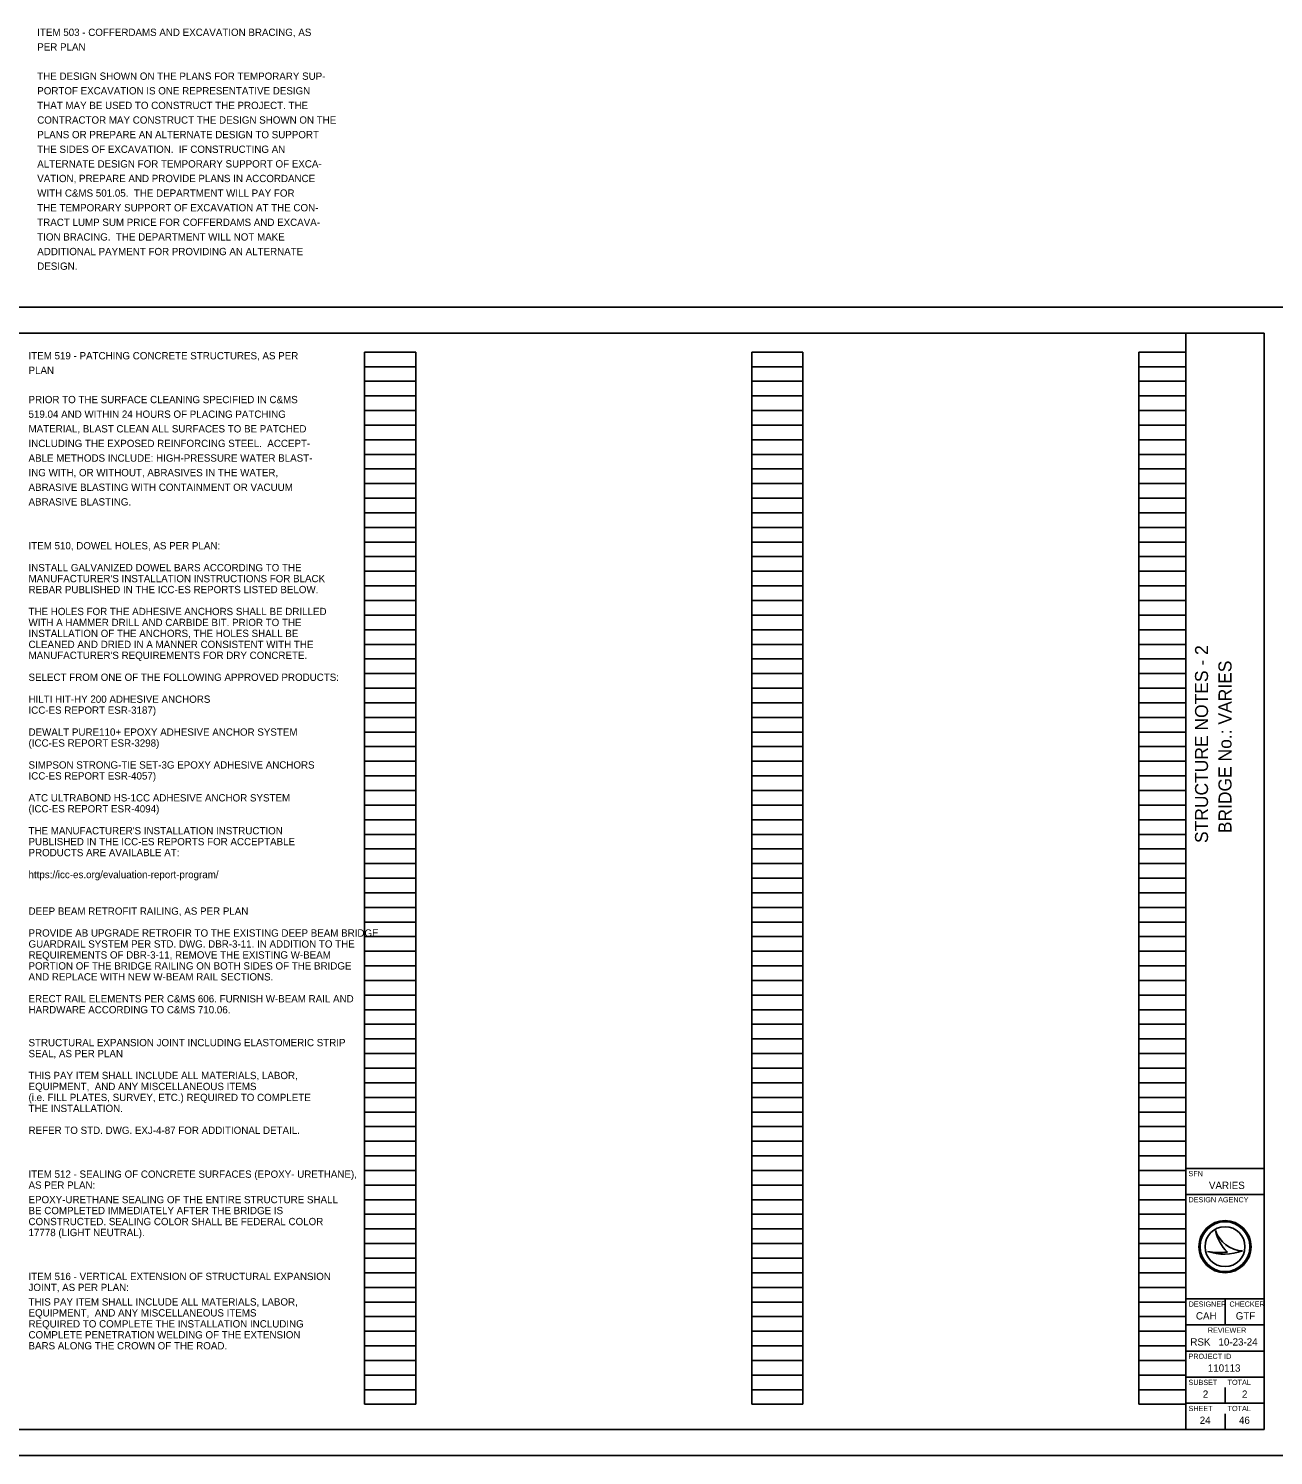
# Model space of a CAD drawing. Extents: x -11.4 to 74.5, y -13.7 to 46.2.
# Drawn here: x 9.82 to 33.68, y 0 to 27.34 of the extents above; entities that cross this region are included whole.
import ezdxf

# ---------------------------------------------------------------- set-up
doc = ezdxf.new("R2010")
doc.units = 0
for name, color, linetype in [('SC_Scratch1', 7, 'Continuous'), ('SH_Border', 7, 'Continuous'), ('SH_Cut_Line', 7, 'Continuous'), ('SH_Data', 7, 'Continuous'), ('SH_Text', 7, 'Continuous')]:
    doc.layers.add(name, color=color, linetype=linetype)

msp = doc.modelspace()

# ---------------------------------------------------------------- linework, layer by layer
at = {"layer": 'SC_Scratch1'}
for p, q in [((16.26, 0.98), (16.26, 21.14)), ((16.26, 21.14), (17.24, 21.14)), ((17.24, 0.98), (17.24, 21.14)), ((23.68, 0.98), (23.68, 21.14)), ((23.68, 21.14), (24.66, 21.14)), ((24.66, 0.98), (24.66, 21.14)), ((31.1, 0.98), (31.1, 21.14)), ((31.1, 21.14), (32, 21.14)), ((32, 0.98), (32, 21.14)), ((16.26, 20.86), (17.24, 20.86)), ((23.68, 20.86), (24.66, 20.86)), ((31.1, 20.86), (32, 20.86)), ((16.26, 20.58), (17.24, 20.58)), ((23.68, 20.58), (24.66, 20.58)), ((31.1, 20.58), (32, 20.58)), ((16.26, 20.3), (17.24, 20.3)), ((23.68, 20.3), (24.66, 20.3)), ((31.1, 20.3), (32, 20.3)), ((16.26, 20.02), (17.24, 20.02)), ((23.68, 20.02), (24.66, 20.02)), ((31.1, 20.02), (32, 20.02)), ((16.26, 19.74), (17.24, 19.74)), ((23.68, 19.74), (24.66, 19.74)), ((31.1, 19.74), (32, 19.74)), ((16.26, 19.46), (17.24, 19.46)), ((23.68, 19.46), (24.66, 19.46)), ((31.1, 19.46), (32, 19.46)), ((16.26, 19.18), (17.24, 19.18)), ((23.68, 19.18), (24.66, 19.18)), ((31.1, 19.18), (32, 19.18)), ((16.26, 18.9), (17.24, 18.9)), ((23.68, 18.9), (24.66, 18.9)), ((31.1, 18.9), (32, 18.9)), ((16.26, 18.62), (17.24, 18.62)), ((23.68, 18.62), (24.66, 18.62)), ((31.1, 18.62), (32, 18.62)), ((16.26, 18.34), (17.24, 18.34)), ((23.68, 18.34), (24.66, 18.34)), ((31.1, 18.34), (32, 18.34)), ((16.26, 18.06), (17.24, 18.06)), ((23.68, 18.06), (24.66, 18.06)), ((31.1, 18.06), (32, 18.06)), ((16.26, 17.78), (17.24, 17.78)), ((23.68, 17.78), (24.66, 17.78)), ((31.1, 17.78), (32, 17.78)), ((16.26, 17.5), (17.24, 17.5)), ((23.68, 17.5), (24.66, 17.5)), ((31.1, 17.5), (32, 17.5)), ((16.26, 17.22), (17.24, 17.22)), ((23.68, 17.22), (24.66, 17.22)), ((31.1, 17.22), (32, 17.22)), ((16.26, 16.94), (17.24, 16.94)), ((23.68, 16.94), (24.66, 16.94)), ((31.1, 16.94), (32, 16.94)), ((16.26, 16.66), (17.24, 16.66)), ((23.68, 16.66), (24.66, 16.66)), ((31.1, 16.66), (32, 16.66)), ((16.26, 16.38), (17.24, 16.38)), ((23.68, 16.38), (24.66, 16.38)), ((31.1, 16.38), (32, 16.38)), ((16.26, 16.1), (17.24, 16.1)), ((23.68, 16.1), (24.66, 16.1)), ((31.1, 16.1), (32, 16.1)), ((16.26, 15.82), (17.24, 15.82)), ((23.68, 15.82), (24.66, 15.82)), ((31.1, 15.82), (32, 15.82)), ((16.26, 15.54), (17.24, 15.54)), ((23.68, 15.54), (24.66, 15.54)), ((31.1, 15.54), (32, 15.54)), ((16.26, 15.26), (17.24, 15.26)), ((23.68, 15.26), (24.66, 15.26)), ((31.1, 15.26), (32, 15.26)), ((16.26, 14.98), (17.24, 14.98)), ((23.68, 14.98), (24.66, 14.98)), ((31.1, 14.98), (32, 14.98)), ((16.26, 14.7), (17.24, 14.7)), ((23.68, 14.7), (24.66, 14.7)), ((31.1, 14.7), (32, 14.7)), ((16.26, 14.42), (17.24, 14.42)), ((23.68, 14.42), (24.66, 14.42)), ((31.1, 14.42), (32, 14.42)), ((16.26, 14.14), (17.24, 14.14)), ((23.68, 14.14), (24.66, 14.14)), ((31.1, 14.14), (32, 14.14)), ((16.26, 13.86), (17.24, 13.86)), ((23.68, 13.86), (24.66, 13.86)), ((31.1, 13.86), (32, 13.86)), ((16.26, 13.58), (17.24, 13.58)), ((23.68, 13.58), (24.66, 13.58)), ((31.1, 13.58), (32, 13.58)), ((16.26, 13.3), (17.24, 13.3)), ((23.68, 13.3), (24.66, 13.3)), ((31.1, 13.3), (32, 13.3)), ((16.26, 13.02), (17.24, 13.02)), ((23.68, 13.02), (24.66, 13.02)), ((31.1, 13.02), (32, 13.02)), ((16.26, 12.74), (17.24, 12.74)), ((23.68, 12.74), (24.66, 12.74)), ((31.1, 12.74), (32, 12.74)), ((16.26, 12.46), (17.24, 12.46)), ((23.68, 12.46), (24.66, 12.46)), ((31.1, 12.46), (32, 12.46)), ((16.26, 12.18), (17.24, 12.18)), ((23.68, 12.18), (24.66, 12.18)), ((31.1, 12.18), (32, 12.18)), ((16.26, 11.9), (17.24, 11.9)), ((23.68, 11.9), (24.66, 11.9)), ((31.1, 11.9), (32, 11.9)), ((16.26, 11.62), (17.24, 11.62)), ((23.68, 11.62), (24.66, 11.62)), ((31.1, 11.62), (32, 11.62)), ((16.26, 11.34), (17.24, 11.34)), ((23.68, 11.34), (24.66, 11.34)), ((31.1, 11.34), (32, 11.34)), ((16.26, 11.06), (17.24, 11.06)), ((23.68, 11.06), (24.66, 11.06)), ((31.1, 11.06), (32, 11.06)), ((16.26, 10.78), (17.24, 10.78)), ((23.68, 10.78), (24.66, 10.78)), ((31.1, 10.78), (32, 10.78)), ((16.26, 10.5), (17.24, 10.5)), ((23.68, 10.5), (24.66, 10.5)), ((31.1, 10.5), (32, 10.5)), ((16.26, 10.22), (17.24, 10.22)), ((23.68, 10.22), (24.66, 10.22)), ((31.1, 10.22), (32, 10.22)), ((16.26, 9.94), (17.24, 9.94)), ((23.68, 9.94), (24.66, 9.94)), ((31.1, 9.94), (32, 9.94)), ((16.26, 9.66), (17.24, 9.66)), ((23.68, 9.66), (24.66, 9.66)), ((31.1, 9.66), (32, 9.66)), ((16.26, 9.38), (17.24, 9.38)), ((23.68, 9.38), (24.66, 9.38)), ((31.1, 9.38), (32, 9.38)), ((16.26, 9.1), (17.24, 9.1)), ((23.68, 9.1), (24.66, 9.1)), ((31.1, 9.1), (32, 9.1)), ((16.26, 8.82), (17.24, 8.82)), ((23.68, 8.82), (24.66, 8.82)), ((31.1, 8.82), (32, 8.82)), ((16.26, 8.54), (17.24, 8.54)), ((23.68, 8.54), (24.66, 8.54)), ((31.1, 8.54), (32, 8.54)), ((16.26, 8.26), (17.24, 8.26)), ((23.68, 8.26), (24.66, 8.26)), ((31.1, 8.26), (32, 8.26)), ((16.26, 7.98), (17.24, 7.98)), ((23.68, 7.98), (24.66, 7.98)), ((31.1, 7.98), (32, 7.98)), ((16.26, 7.7), (17.24, 7.7)), ((23.68, 7.7), (24.66, 7.7)), ((31.1, 7.7), (32, 7.7)), ((16.26, 7.42), (17.24, 7.42)), ((23.68, 7.42), (24.66, 7.42)), ((31.1, 7.42), (32, 7.42)), ((16.26, 7.14), (17.24, 7.14)), ((23.68, 7.14), (24.66, 7.14)), ((31.1, 7.14), (32, 7.14)), ((16.26, 6.86), (17.24, 6.86)), ((23.68, 6.86), (24.66, 6.86)), ((31.1, 6.86), (32, 6.86)), ((16.26, 6.58), (17.24, 6.58)), ((23.68, 6.58), (24.66, 6.58)), ((31.1, 6.58), (32, 6.58)), ((16.26, 6.3), (17.24, 6.3)), ((23.68, 6.3), (24.66, 6.3)), ((31.1, 6.3), (32, 6.3)), ((16.26, 6.02), (17.24, 6.02)), ((23.68, 6.02), (24.66, 6.02)), ((31.1, 6.02), (32, 6.02)), ((16.26, 5.74), (17.24, 5.74)), ((23.68, 5.74), (24.66, 5.74)), ((31.1, 5.74), (32, 5.74)), ((16.26, 5.46), (17.24, 5.46)), ((23.68, 5.46), (24.66, 5.46)), ((31.1, 5.46), (32, 5.46)), ((16.26, 5.18), (17.24, 5.18)), ((23.68, 5.18), (24.66, 5.18)), ((31.1, 5.18), (32, 5.18)), ((16.26, 4.9), (17.24, 4.9)), ((23.68, 4.9), (24.66, 4.9)), ((31.1, 4.9), (32, 4.9)), ((16.26, 4.62), (17.24, 4.62)), ((23.68, 4.62), (24.66, 4.62)), ((31.1, 4.62), (32, 4.62)), ((16.26, 4.34), (17.24, 4.34)), ((23.68, 4.34), (24.66, 4.34)), ((31.1, 4.34), (32, 4.34)), ((16.26, 4.06), (17.24, 4.06)), ((23.68, 4.06), (24.66, 4.06)), ((31.1, 4.06), (32, 4.06)), ((16.26, 3.78), (17.24, 3.78)), ((23.68, 3.78), (24.66, 3.78)), ((31.1, 3.78), (32, 3.78)), ((16.26, 3.5), (17.24, 3.5)), ((23.68, 3.5), (24.66, 3.5)), ((31.1, 3.5), (32, 3.5)), ((16.26, 3.22), (17.24, 3.22)), ((23.68, 3.22), (24.66, 3.22)), ((31.1, 3.22), (32, 3.22)), ((16.26, 2.94), (17.24, 2.94)), ((23.68, 2.94), (24.66, 2.94)), ((31.1, 2.94), (32, 2.94)), ((16.26, 2.66), (17.24, 2.66)), ((23.68, 2.66), (24.66, 2.66)), ((31.1, 2.66), (32, 2.66)), ((16.26, 2.38), (17.24, 2.38)), ((23.68, 2.38), (24.66, 2.38)), ((31.1, 2.38), (32, 2.38)), ((16.26, 2.1), (17.24, 2.1)), ((23.68, 2.1), (24.66, 2.1)), ((31.1, 2.1), (32, 2.1)), ((16.26, 1.82), (17.24, 1.82)), ((23.68, 1.82), (24.66, 1.82)), ((31.1, 1.82), (32, 1.82)), ((16.26, 1.54), (17.24, 1.54)), ((23.68, 1.54), (24.66, 1.54)), ((31.1, 1.54), (32, 1.54)), ((16.26, 1.26), (17.24, 1.26)), ((23.68, 1.26), (24.66, 1.26)), ((31.1, 1.26), (32, 1.26)), ((16.26, 0.98), (17.24, 0.98)), ((23.68, 0.98), (24.66, 0.98)), ((31.1, 0.98), (32, 0.98))]:
    msp.add_line(p, q, dxfattribs=at)
at = {"layer": 'SH_Border'}
for p, q in [((32, 0.5), (32, 21.5)), ((32, 5.5), (33.5, 5.5)), ((32, 5), (33.5, 5)), ((32, 3), (33.5, 3)), ((32.75, 3), (32.75, 2.5)), ((32, 2.5), (33.5, 2.5)), ((32, 2), (33.5, 2)), ((32, 1.5), (33.5, 1.5)), ((32, 1), (33.5, 1))]:
    msp.add_line(p, q, dxfattribs=at)
msp.add_lwpolyline([(1.5, 21.5), (33.5, 21.5), (33.5, 0.5), (1.5, 0.5)], close=True, dxfattribs=at)
at = {"layer": 'SH_Cut_Line'}
msp.add_lwpolyline([(0, 0), (34, 0), (34, 22), (0, 22)], close=True, dxfattribs=at)
at = {"layer": 'SH_Data'}
for p, q in [((32.567, 4.31), (32.567, 4.31)), ((32.417, 3.91), (32.417, 3.91)), ((32.75, 4), (32.75, 4)), ((33.087, 3.919), (33.087, 3.919)), ((32.75, 1), (32.75, 1.3)), ((32.375, 0.675), (32.375, 0.675)), ((32.75, 0.5), (32.75, 0.8))]:
    msp.add_line(p, q, dxfattribs=at)
for radius in [0.5, 0.477, 0.477, 0.382]:
    msp.add_circle((32.75, 4), radius, dxfattribs=at)
for centre, radius, start, end in [((33.116, 4.498), 0.58, 198.9257, 198.9319), ((33.347, 4.47), 0.796, 191.6379, 191.6421), ((33.116, 4.498), 0.58, 198.9319, 267.1657), ((33.347, 4.47), 0.796, 191.6421, 226.0947), ((32.739, 4.87), 1.013, 251.4576, 290.0832), ((32.648, 5.154), 1.266, 259.4964, 259.4995), ((32.739, 4.87), 1.013, 251.4527, 251.4576), ((32.648, 5.154), 1.266, 259.4995, 276.6672)]:
    msp.add_arc(centre, radius, start, end, dxfattribs=at)

# ---------------------------------------------------------------- texts
for s, p in [('STRUCTURE NOTES - 2', (32.425, 11.734)), ('BRIDGE No.: VARIES', (32.875, 11.922))]:
    msp.add_text(s, height=0.25, rotation=90, dxfattribs=at).set_placement(p)
for s, height, p in [('SFN', 0.1, (32.05, 5.35)), ('VARIES', 0.14, (32.442, 5.105)), ('DESIGN AGENCY', 0.1, (32.05, 4.85)), ('DESIGNER', 0.1, (32.054, 2.85)), ('CAH', 0.14, (32.193, 2.605)), ('CHECKER', 0.1, (32.835, 2.85)), ('GTF', 0.14, (32.956, 2.605)), ('RSK', 0.14, (32.086, 2.105)), ('REVIEWER', 0.1, (32.422, 2.35)), ('10-23-24', 0.14, (32.625, 2.105)), ('PROJECT ID', 0.1, (32.05, 1.85)), ('110113', 0.14, (32.421, 1.605)), ('SUBSET', 0.1, (32.05, 1.35)), ('TOTAL', 0.1, (32.8, 1.35)), ('2', 0.14, (32.325, 1.105)), ('2', 0.14, (33.075, 1.105)), ('SHEET', 0.1, (32.05, 0.85)), ('TOTAL', 0.1, (32.8, 0.85)), ('24', 0.14, (32.266, 0.605)), ('46', 0.14, (33.018, 0.605))]:
    msp.add_text(s, height=height, dxfattribs=at).set_placement(p)
at = {"layer": 'SH_Text'}
for s, p in [('ITEM 503 - COFFERDAMS AND EXCAVATION BRACING, AS', (9.987, 27.196)), ('PER PLAN', (9.987, 26.916)), ('THE DESIGN SHOWN ON THE PLANS FOR TEMPORARY SUP-', (9.987, 26.356)), ('PORTOF EXCAVATION IS ONE REPRESENTATIVE DESIGN', (9.987, 26.076)), ('THAT MAY BE USED TO CONSTRUCT THE PROJECT. THE', (9.987, 25.796)), ('CONTRACTOR MAY CONSTRUCT THE DESIGN SHOWN ON THE', (9.987, 25.516)), ('PLANS OR PREPARE AN ALTERNATE DESIGN TO SUPPORT', (9.987, 25.236)), ('THE SIDES OF EXCAVATION.  IF CONSTRUCTING AN', (9.987, 24.956)), ('ALTERNATE DESIGN FOR TEMPORARY SUPPORT OF EXCA-', (9.987, 24.676)), ('VATION, PREPARE AND PROVIDE PLANS IN ACCORDANCE', (9.987, 24.396)), ('WITH C&MS 501.05.  THE DEPARTMENT WILL PAY FOR', (9.987, 24.116)), ('THE TEMPORARY SUPPORT OF EXCAVATION AT THE CON-', (9.987, 23.836)), ('TRACT LUMP SUM PRICE FOR COFFERDAMS AND EXCAVA-', (9.987, 23.556)), ('TION BRACING.  THE DEPARTMENT WILL NOT MAKE', (9.987, 23.276)), ('ADDITIONAL PAYMENT FOR PROVIDING AN ALTERNATE', (9.987, 22.996)), ('DESIGN.', (9.987, 22.716)), ('ITEM 519 - PATCHING CONCRETE STRUCTURES, AS PER', (9.82, 21)), ('PLAN', (9.82, 20.72)), ('PRIOR TO THE SURFACE CLEANING SPECIFIED IN C&MS', (9.82, 20.16)), ('519.04 AND WITHIN 24 HOURS OF PLACING PATCHING', (9.82, 19.88)), ('MATERIAL, BLAST CLEAN ALL SURFACES TO BE PATCHED', (9.82, 19.6)), ('INCLUDING THE EXPOSED REINFORCING STEEL.  ACCEPT-', (9.82, 19.32)), ('ABLE METHODS INCLUDE: HIGH-PRESSURE WATER BLAST-', (9.82, 19.04)), ('ING WITH, OR WITHOUT, ABRASIVES IN THE WATER,', (9.82, 18.76)), ('ABRASIVE BLASTING WITH CONTAINMENT OR VACUUM', (9.82, 18.48)), ('ABRASIVE BLASTING.', (9.82, 18.2)), ('ITEM 510, DOWEL HOLES, AS PER PLAN:', (9.82, 17.36)), ('INSTALL GALVANIZED DOWEL BARS ACCORDING TO THE', (9.82, 16.94)), ("MANUFACTURER'S INSTALLATION INSTRUCTIONS FOR BLACK", (9.82, 16.73)), ('REBAR PUBLISHED IN THE ICC-ES REPORTS LISTED BELOW.', (9.82, 16.52)), ('THE HOLES FOR THE ADHESIVE ANCHORS SHALL BE DRILLED', (9.82, 16.1)), ('WITH A HAMMER DRILL AND CARBIDE BIT. PRIOR TO THE', (9.82, 15.89)), ('CLEANED AND DRIED IN A MANNER CONSISTENT WITH THE', (9.82, 15.47)), ('INSTALLATION OF THE ANCHORS, THE HOLES SHALL BE', (9.82, 15.68)), ("MANUFACTURER'S REQUIREMENTS FOR DRY CONCRETE.", (9.82, 15.26)), ('SELECT FROM ONE OF THE FOLLOWING APPROVED PRODUCTS:', (9.82, 14.84)), ('HILTI HIT-HY 200 ADHESIVE ANCHORS', (9.82, 14.42)), ('ICC-ES REPORT ESR-3187)', (9.82, 14.21)), ('(ICC-ES REPORT ESR-3298)', (9.82, 13.58)), ('DEWALT PURE110+ EPOXY ADHESIVE ANCHOR SYSTEM', (9.82, 13.79)), ('SIMPSON STRONG-TIE SET-3G EPOXY ADHESIVE ANCHORS', (9.82, 13.16)), ('ICC-ES REPORT ESR-4057)', (9.82, 12.95)), ('ATC ULTRABOND HS-1CC ADHESIVE ANCHOR SYSTEM', (9.82, 12.53)), ('(ICC-ES REPORT ESR-4094)', (9.82, 12.32)), ("THE MANUFACTURER'S INSTALLATION INSTRUCTION", (9.82, 11.9)), ('PUBLISHED IN THE ICC-ES REPORTS FOR ACCEPTABLE', (9.82, 11.69)), ('PRODUCTS ARE AVAILABLE AT:', (9.82, 11.48)), ('https://icc-es.org/evaluation-report-program/', (9.82, 11.06)), ('DEEP BEAM RETROFIT RAILING, AS PER PLAN', (9.82, 10.36)), ('GUARDRAIL SYSTEM PER STD. DWG. DBR-3-11. IN ADDITION TO THE', (9.82, 9.73)), ('PROVIDE AB UPGRADE RETROFIR TO THE EXISTING DEEP BEAM BRIDGE', (9.82, 9.94)), ('REQUIREMENTS OF DBR-3-11, REMOVE THE EXISTING W-BEAM', (9.82, 9.52)), ('PORTION OF THE BRIDGE RAILING ON BOTH SIDES OF THE BRIDGE', (9.82, 9.31)), ('AND REPLACE WITH NEW W-BEAM RAIL SECTIONS.', (9.82, 9.1)), ('ERECT RAIL ELEMENTS PER C&MS 606. FURNISH W-BEAM RAIL AND', (9.82, 8.68)), ('HARDWARE ACCORDING TO C&MS 710.06.', (9.82, 8.47)), ('STRUCTURAL EXPANSION JOINT INCLUDING ELASTOMERIC STRIP ', (9.82, 7.84)), ('SEAL, AS PER PLAN ', (9.82, 7.63)), ('THIS PAY ITEM SHALL INCLUDE ALL MATERIALS, LABOR, ', (9.82, 7.21)), ('EQUIPMENT,  AND ANY MISCELLANEOUS ITEMS', (9.82, 7)), ('(i.e. FILL PLATES, SURVEY, ETC.) REQUIRED TO COMPLETE', (9.82, 6.79)), ('THE INSTALLATION.', (9.82, 6.58)), ('REFER TO STD. DWG. EXJ-4-87 FOR ADDITIONAL DETAIL.', (9.82, 6.16)), ('AS PER PLAN:', (9.82, 5.11)), ('ITEM 512 - SEALING OF CONCRETE SURFACES (EPOXY- URETHANE), ', (9.82, 5.32)), ('EPOXY-URETHANE SEALING OF THE ENTIRE STRUCTURE SHALL ', (9.82, 4.832)), ('BE COMPLETED IMMEDIATELY AFTER THE BRIDGE IS ', (9.82, 4.622)), ('CONSTRUCTED. SEALING COLOR SHALL BE FEDERAL COLOR ', (9.82, 4.412)), ('17778 (LIGHT NEUTRAL).', (9.82, 4.202)), ('JOINT, AS PER PLAN:', (9.82, 3.15)), ('ITEM 516 - VERTICAL EXTENSION OF STRUCTURAL EXPANSION ', (9.82, 3.36)), ('THIS PAY ITEM SHALL INCLUDE ALL MATERIALS, LABOR, ', (9.82, 2.872)), ('EQUIPMENT,  AND ANY MISCELLANEOUS ITEMS', (9.82, 2.662)), ('REQUIRED TO COMPLETE THE INSTALLATION INCLUDING', (9.82, 2.452)), ('COMPLETE PENETRATION WELDING OF THE EXTENSION', (9.82, 2.242)), ('BARS ALONG THE CROWN OF THE ROAD.', (9.82, 2.032))]:
    msp.add_text(s, height=0.14, dxfattribs=at).set_placement(p)

doc.saveas('drawing.dxf')
